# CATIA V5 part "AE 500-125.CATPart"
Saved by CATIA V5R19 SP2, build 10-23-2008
Part number: AE 500-125
Bounding box of the stored display mesh (mm): x -22.494 to 22.494, y -22.494 to 22.494, z 0 to 300
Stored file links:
  C:\Users\Bora\Desktop\3D Katı model\AE serisi\AE 500\AE 500-125.CATPart
  C:\Program Files\Dassault Systemes\B19\intel_a\reffiles\standard\MetricThickPitch.txt
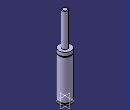
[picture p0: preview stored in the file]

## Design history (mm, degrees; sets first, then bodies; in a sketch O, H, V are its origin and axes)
Body1 (main body)
  Sketch1 on yz-plane, origin (0, 0, 0), H (0, 1, 0), V (0, 0, 1)
    point P1 (22.5, 158.5)
    point P8 (22.5, 160.5)
    point P9 (22.5, 160.5)
    point P10 (22.5, 158.5)
    point P11 (10, 298)
    point P13 (10, 298)
    line L1 (22.5, 158.5) -> (22.5, 8)
    line L2 (22.5, 4) -> (22.5, 0)
    line L3 (20, 8) -> (20, 4)
    line L4 (22.5, 174) -> (22.5, 160.5)
    arc A1 centre (22.5, 159.5) radius 1 from (22.5, 160.5) to (22.5, 158.5) ccw
    line L5 (10, 298) -> (10, 174)
    arc A2 centre (8, 298) radius 2 from (10, 298) to (8, 300) ccw
    line L6 (8, 300) -> (0, 300)
    point P15 (0, 300)
    line L7 (10, 174) -> (22.5, 174)
    line L8 (0, 0) -> (22.5, 0)
    line L9 (20, 8) -> (22.5, 8)
    line L10 (20, 4) -> (22.5, 4)
    coincidence: P15 V, P1 P10, P8 P9, P11 P13
    tangency: L6 A2
    horizontal: L7 H, L8 H, L9 H, L10 H
  Shaft1: profile Sketch1, axis Sketch1.V, angle 360
  Sketch2 on face of Shaft1 from Sketch1.L8, origin (0, 0, 0), H (1, 0, 0), V (0, -1, 0)
    point P1 (10, 0)
    distance P1 V = 10
  Hole1: placed by Sketch2, at (10, 0, 0) direction (0, 0, 1), diameter 6.647, depth 13, threaded "M8", thread diameter 8, thread depth 13, pitch 1.25
  CircPattern1: of Hole1, instances 2, angular step 180, axis from xy-plane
